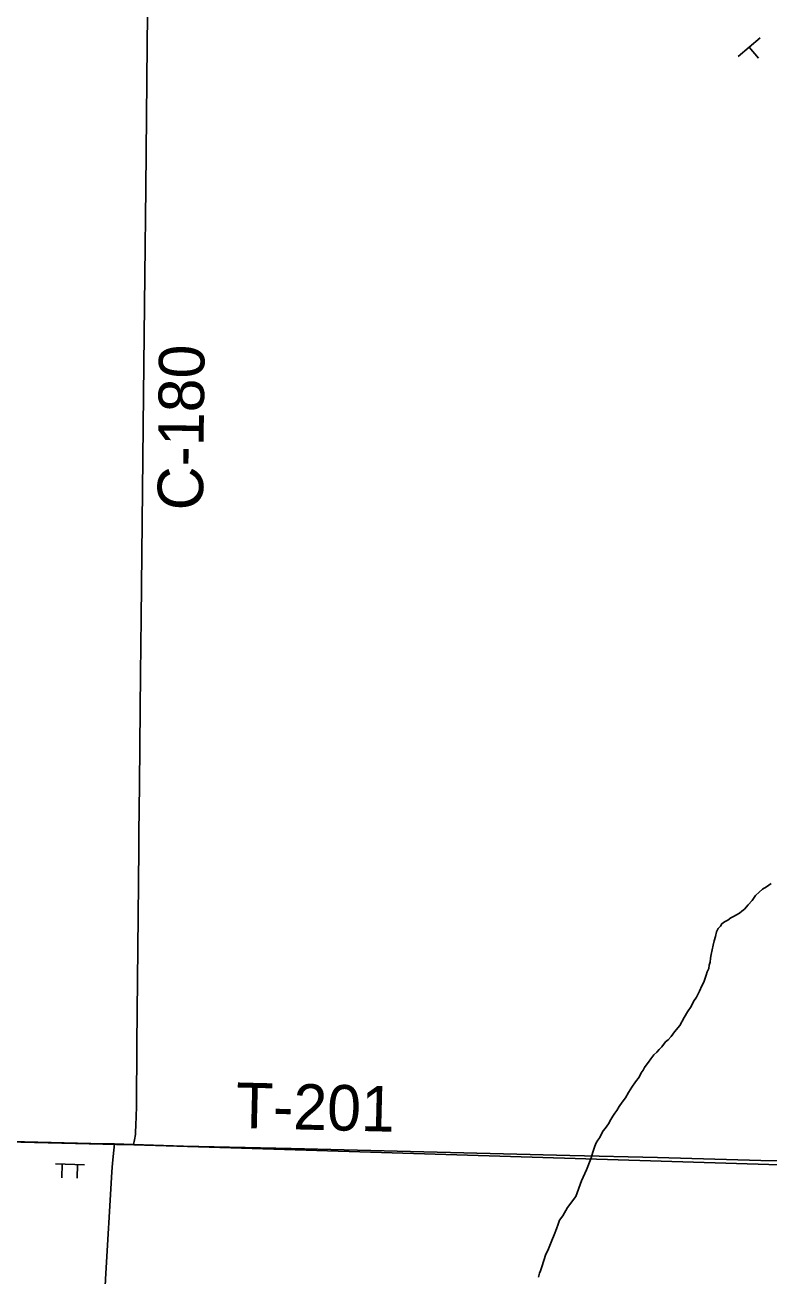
# Model space of a CAD drawing. Extents: x 1 to 1675, y -2 to 1113.
# Drawn here: x 1656.36 to 1660.44, y 1091.69 to 1098.56 of the extents above; entities that cross this region are included whole.
import ezdxf

# ---------------------------------------------------------------- set-up
doc = ezdxf.new("R2010")
doc.units = 0
for name, color, linetype in [('GM_X_County_Road_Text', 7, 'Continuous'), ('GM_X_Township', 7, 'Continuous'), ('GM_X_Township_Road_Text', 7, 'Continuous'), ('SC_Scratch1', 7, 'Continuous'), ('SN_P_Signs', 7, 'Continuous'), ('SN_P_Text', 7, 'Continuous')]:
    doc.layers.add(name, color=color, linetype=linetype)

msp = doc.modelspace()

# ---------------------------------------------------------------- linework, layer by layer
at = {"layer": 'GM_X_Township'}
msp.add_lwpolyline([(1653.1763, 1092.4976), (1656.8592, 1092.4086), (1656.9549, 1092.4071), (1660.4424, 1092.2976), (1663.9517, 1092.2334), (1668.658, 1092.1116), (1671.0761, 1092.0354), (1672.2022, 1091.993)], dxfattribs=at)
at = {"layer": 'SC_Scratch1'}
for points in [[(1660.4565, 1093.8425), (1660.4297, 1093.8238), (1660.4082, 1093.8105), (1660.3895, 1093.7945), (1660.3707, 1093.7759), (1660.3519, 1093.7492), (1660.3304, 1093.7251), (1660.309, 1093.7011), (1660.2956, 1093.6905), (1660.2822, 1093.6798), (1660.2661, 1093.6692), (1660.25, 1093.6612), (1660.2339, 1093.6532), (1660.2179, 1093.6399), (1660.1991, 1093.6319), (1660.1857, 1093.6213), (1660.1777, 1093.6079), (1660.1642, 1093.5946), (1660.1562, 1093.5759), (1660.1508, 1093.5518), (1660.1427, 1093.5278)], [(1660.1427, 1093.5278), (1660.1373, 1093.5037), (1660.1319, 1093.477), (1660.1265, 1093.4529), (1660.1237, 1093.4315), (1660.121, 1093.4101), (1660.1156, 1093.3941), (1660.1129, 1093.3753), (1660.1048, 1093.3566), (1660.0994, 1093.3379), (1660.094, 1093.3219), (1660.086, 1093.3005), (1660.0752, 1093.2791), (1660.0618, 1093.2498), (1660.0456, 1093.2177), (1660.0295, 1093.1937), (1660.0161, 1093.167), (1659.9973, 1093.1376), (1659.9785, 1093.1055), (1659.9543, 1093.0628), (1659.9248, 1093.0281), (1659.906, 1093.0014), (1659.8899, 1092.9828), (1659.8765, 1092.9721), (1659.855, 1092.9454), (1659.8416, 1092.9294), (1659.8282, 1092.9161), (1659.8121, 1092.9001), (1659.796, 1092.8787), (1659.7826, 1092.86), (1659.7692, 1092.844), (1659.7611, 1092.8307), (1659.7531, 1092.8173), (1659.7423, 1092.8013), (1659.7316, 1092.7773), (1659.7101, 1092.7532), (1659.6913, 1092.7239), (1659.6725, 1092.6945), (1659.6564, 1092.6651), (1659.6376, 1092.6411), (1659.6215, 1092.6171), (1659.6081, 1092.5957), (1659.5973, 1092.5797), (1659.5866, 1092.5637), (1659.5758, 1092.545), (1659.5624, 1092.5209), (1659.5436, 1092.4969), (1659.5329, 1092.4836), (1659.5248, 1092.4676), (1659.5141, 1092.4462), (1659.5033, 1092.4328), (1659.4953, 1092.4168), (1659.4872, 1092.3981), (1659.4791, 1092.3714), (1659.4656, 1092.3286), (1659.4414, 1092.2698), (1659.4145, 1092.2084), (1659.3822, 1092.1229), (1659.3366, 1092.0615), (1659.3124, 1092.0161), (1659.2936, 1091.9921), (1659.2855, 1091.9707), (1659.2774, 1091.9439), (1659.264, 1091.9119), (1659.2505, 1091.8798), (1659.2398, 1091.8531), (1659.229, 1091.8264), (1659.2183, 1091.805), (1659.1967, 1091.7355), (1659.1886, 1091.7141), (1659.1832, 1091.7008), (1659.1778, 1091.6794)]]:
    msp.add_lwpolyline(points, dxfattribs=at)
at = {"layer": 'SN_P_Signs'}
for p, q in [((1660.3965, 1098.4896), (1660.274, 1098.3866)), ((1660.3352, 1098.4381), (1660.3868, 1098.3768)), ((1656.5251, 1092.3023), (1656.6848, 1092.2971)), ((1656.562, 1092.3011), (1656.5596, 1092.2258)), ((1656.6463, 1092.2984), (1656.6439, 1092.2231))]:
    msp.add_line(p, q, dxfattribs=at)
for points in [[(1656.9539, 1092.4077), (1656.9591, 1092.4332), (1656.9636, 1092.4628), (1656.965, 1092.4774), (1656.9669, 1092.5129), (1656.97, 1092.6154), (1656.9719, 1092.9605), (1656.9793, 1093.661), (1656.9822, 1094.0329), (1656.9825, 1094.1201), (1656.9871, 1094.3825), (1656.9878, 1094.6012), (1656.9921, 1094.995), (1656.9954, 1095.3015), (1657.0088, 1096.5272), (1657.0119, 1096.8554), (1657.0164, 1097.1823), (1657.0216, 1097.6632), (1657.0277, 1098.4513), (1657.0348, 1099.1076)], [(1656.9539, 1092.4077), (1656.9591, 1092.4332), (1656.9636, 1092.4628), (1656.965, 1092.4774), (1656.9669, 1092.5129), (1656.97, 1092.6154), (1656.9719, 1092.9605), (1656.9793, 1093.661), (1656.9822, 1094.0329), (1656.9825, 1094.1201), (1656.9871, 1094.3825), (1656.9878, 1094.6012), (1656.9921, 1094.995), (1656.9954, 1095.3015), (1657.0088, 1096.5272), (1657.0119, 1096.8554), (1657.0164, 1097.1823), (1657.0216, 1097.6632), (1657.0277, 1098.4513), (1657.0348, 1099.1076)], [(1656.6538, 1088.9713), (1656.6824, 1089.549), (1656.7502, 1090.7723), (1656.779, 1091.2527), (1656.8004, 1091.6678), (1656.8346, 1092.2577), (1656.8383, 1092.3049), (1656.8451, 1092.3768), (1656.8483, 1092.4109)], [(1656.6538, 1088.9713), (1656.6824, 1089.549), (1656.7502, 1090.7723), (1656.779, 1091.2527), (1656.8004, 1091.6678), (1656.8346, 1092.2577), (1656.8383, 1092.3049), (1656.8451, 1092.3768), (1656.8483, 1092.4109)], [(1656.8483, 1092.4109), (1656.9539, 1092.4077)], [(1656.8483, 1092.4109), (1656.9539, 1092.4077)]]:
    msp.add_lwpolyline(points, dxfattribs=at)
at = {"layer": 'SN_P_Text'}
for points in [[(1653.1763, 1092.4975), (1653.4015, 1092.4929), (1654.3201, 1092.4717), (1654.5825, 1092.4645), (1655.2605, 1092.4486), (1655.8291, 1092.4348), (1656.3539, 1092.4224), (1656.7913, 1092.4126), (1656.8483, 1092.4109)], [(1653.1763, 1092.4975), (1653.4015, 1092.4929), (1654.3201, 1092.4717), (1654.5825, 1092.4645), (1655.2605, 1092.4486), (1655.8291, 1092.4348), (1656.3539, 1092.4224), (1656.7913, 1092.4126), (1656.8483, 1092.4109)], [(1656.9539, 1092.4077), (1657.2287, 1092.3994), (1657.8192, 1092.386), (1659.35, 1092.3476), (1659.8311, 1092.3358), (1660.3997, 1092.32), (1660.4916, 1092.3184)], [(1656.9539, 1092.4077), (1657.2287, 1092.3994), (1657.8192, 1092.386), (1659.35, 1092.3476), (1659.8311, 1092.3358), (1660.3997, 1092.32), (1660.4916, 1092.3184)]]:
    msp.add_lwpolyline(points, dxfattribs=at)

# ---------------------------------------------------------------- texts
at = {"layer": 'GM_X_County_Road_Text'}
msp.add_text('C-180', height=0.25, rotation=89.44765, dxfattribs=at).set_placement((1657.335, 1095.8916))
at = {"layer": 'GM_X_Township_Road_Text'}
msp.add_text('T-201', height=0.25, rotation=358.59569, dxfattribs=at).set_placement((1657.5131, 1092.4993))

doc.saveas('drawing.dxf')
